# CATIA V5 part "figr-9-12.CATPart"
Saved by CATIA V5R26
Part number: Part2
Bounding box of the stored display mesh (mm): x -96.75 to 0, y -83.031 to 83.031, z -58.031 to 58.031
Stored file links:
  D:\_Deepak\CATIA\CATIA V5-6R2016_Deepak\Resources\Part files\Partfiles\c09_catia_v5_6r2016_prt\figr-9-12.CATPart
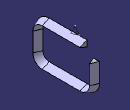
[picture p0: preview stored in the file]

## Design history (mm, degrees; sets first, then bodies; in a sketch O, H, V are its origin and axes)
Body1 (main body)
  Sketch1 on yz-plane, origin (0, 0, 0), H (0, 1, 0), V (0, 0, 1)
    point P1 (-75, 50)
    line L1 (-50, 50) -> (50, 50)
    line L2 (75, 25) -> (75, -25)
    line L3 (50, -50) -> (-50, -50)
    line L4 (-75, -25) -> (-75, 25)
    point P2 (75, 50)
    point P3 (75, -50)
    arc A1 centre (-50, 25) radius 25 from (-50, 50) to (-75, 25) ccw
    arc A2 centre (-50, -25) radius 25 from (-50, -50) to (-75, -25) cw
    arc A3 centre (50, -25) radius 25 from (50, -50) to (75, -25) ccw
    distance V L4 = 75
    distance H L1 = 50
    distance P1 P2 = 150
    radius A1 = 25
    radius A2 = 25
    distance P2 P3 = 100
    radius A3 = 25
    horizontal: L1 H, L3 H
    vertical: L2 V, L4 V
    coincidence: L1 P1, L4 P1, L3 P3, L2 P3, L2 P2, L1 P2
    tangency: A1 L1, A1 L4, A2 L3, A2 L4, A3 L3, A3 L2
  Plane1: type Angle, RefPlane yz-plane, Direction Sketch1.V, Angle 31
  Plane2: type Offset, RefPlane Plane1, Offset -108
  Sketch2 on Plane2, origin (-92.5741, -55.6241, 0), H (-0.515, 0.8572, 0), V (0, 0, 1)
    line L1 (0, 0) -> (-8.0309, -18.5626)
    line L2 (-8.0309, -18.5626) -> (8.1085, -18.5626)
    line L3 (8.1085, -18.5626) -> (0, 0)
    horizontal: L2 H
  Rib1: profile Sketch2, centre curve Sketch1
